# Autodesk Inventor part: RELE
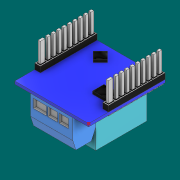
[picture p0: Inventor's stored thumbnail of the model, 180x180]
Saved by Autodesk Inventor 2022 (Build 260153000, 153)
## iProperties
Created: 2021-11
Part Number: RELE
Material: Generic
Document SubType Name: Modeling
Designer: santi
Density: 1 g/cm^3
Appearance: Default
Author: santi
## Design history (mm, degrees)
sketch "Sketch1"
  geometry: L1 (0, 0)-(0, -31); L2 (0, -31)-(26, -31); L3 (26, -31)-(26, 0); L4 (26, 0)-(0, 0)
  constraints: 8 end point, 3 perpendicular, 1 vertical
  dimensions: "d0" = 31 distance of L1.start L1.end; "d1" = 26 distance of L1.end L2.end
extrude "Extrusion1" new body sketch "Sketch1" distance "d2" = 1; taper "d3" = 0 deg
fillet "Fillet1" dims "d4" = 2
sketch "Sketch3"
  geometry: L1 (-26, 0)-(0, 0) reference; L2 (0, 0)-(0, 7); L3 (0, 0)-(0, 29) reference; L4 (0, 7)-(-2, 7); L5 (-2, 7)-(-2, 27); L6 (-2, 27)-(0, 27); L7 (0, 7)-(0, 27); L8 (-13, 0)-(-13, 9.207); L9 (-26, 0)-(-26, 7); L10 (-26, 0)-(-26, 29); L11 (-26, 7)-(-24, 7); L12 (-24, 7)-(-24, 27); L13 (-24, 27)-(-26, 27); L14 (-26, 7)-(-26, 27)
  constraints: 24 end point, 5 symmetric about line, 4 point on line, 3 perpendicular, 2 vertical, 1 midpoint
  dimensions: "d12" = 7 distance of L1.end L2.end; "d13" = 2 distance of L2.end L4.end; "d14" = 20 distance of L4.end L5.end
extrude "Extrusion3" join sketch "Sketch3" distance "d15" = 9; taper "d16" = 0 deg
sketch "Sketch5"
  geometry: L1 (9, 1)-(17, 1) reference; L2 (17, 1)-(9, 1); L3 (9, 1)-(11, 1); L4 (9, 1)-(10, 1); L5 (9, 1)-(9, 3) reference; L6 (13, 1)-(13, 2.179); L7 (17, 1)-(16, 1); L8 (17, 1)-(17, 3); A1 r 1 centre (10, 2) between (9, 2) and (10, 1); A2 r 1 centre (16, 2) between (16, 1) and (17, 2); 3 further points
  constraints: 12 end point, 4 point on circle, 4 symmetric about line, 3 midpoint, 2 centre point, 1 collinear, 1 point on line, 1 tangent, 1 vertical, 1 other
  dimensions: "d23" = 1 distance of L1.start L4.end
extrude "Extrusion5" cut sketch "Sketch5" distance "d24" = 5; taper "d25" = 0 deg
sketch "Sketch9"
  geometry: L1 (-24, 27)-(-26, 27) reference; L2 (-26, 27)-(-26, 7) reference; L3 (-26, 7)-(-24, 7) reference; L4 (-24, 7)-(-24, 27) reference; L5 (-25.7, 26.7)-(-24.3, 26.7); L6 (-24.3, 25.1)-(-24.3, 7.3); L7 (-24.3, 7.3)-(-25.7, 7.3); L8 (-25.7, 7.3)-(-25.7, 26.7); L9 (-24.3, 26.7)-(-24.3, 25.1); L10 (-24.3, 25.1)-(-25.7, 25.1); L11 (-25.7, 24.8)-(-24.3, 24.8); L12 (-24, 24.9)-(-24, 26.7); L13 (-25.7, 23.2)-(-24.3, 23.2); L14 (-25.7, 22.9)-(-24.3, 22.9); L15 (-25.7, 21.3)-(-24.3, 21.3); L16 (-25.7, 21)-(-24.3, 21); L17 (-25.7, 19.4)-(-24.3, 19.4); L18 (-25.7, 19.1)-(-24.3, 19.1); L19 (-25.7, 17.5)-(-24.3, 17.5); L20 (-25.7, 17.2)-(-24.3, 17.2); L21 (-25.7, 15.6)-(-24.3, 15.6); L22 (-25.7, 15.3)-(-24.3, 15.3); L23 (-25.7, 13.7)-(-24.3, 13.7); L24 (-25.7, 13.4)-(-24.3, 13.4); L25 (-25.7, 11.8)-(-24.3, 11.8); L26 (-25.7, 11.5)-(-24.3, 11.5); L27 (-25.7, 9.9)-(-24.3, 9.9); L28 (-25.7, 9.5)-(-24.3, 9.5); 34 further points
  constraints: 48 end point, 16 parallel, 2 point on line, 1 perpendicular, 1 other
  dimensions: "d38" = 0.3 distance between parallel lines of L1 L5; "d39" = 1.6 distance of L6.start L5.end; "d40" = 0.3 distance between parallel lines of L10 L11; "d41" = 1.6 distance between parallel lines of L11 L13; "d42" = 0.3 distance between parallel lines of L13 L14; "d43" = 1.6 distance between parallel lines of L14 L15; "d44" = 0.3 distance between parallel lines of L15 L16; "d45" = 1.6 distance between parallel lines of L16 L17; "d46" = 0.3 distance between parallel lines of L17 L18; "d47" = 1.6 distance between parallel lines of L18 L19; "d48" = 0.3 distance between parallel lines of L19 L20; "d49" = 1.6 distance between parallel lines of L20 L21; "d50" = 0.3 distance between parallel lines of L21 L22; "d51" = 1.6 distance between parallel lines of L22 L23; "d52" = 0.3 distance between parallel lines of L23 L24; "d53" = 1.6 distance between parallel lines of L24 L25; "d54" = 0.3 distance between parallel lines of L25 L26; "d55" = 1.6 distance between parallel lines of L26 L27; "d56" = 0.4 distance between parallel lines of L27 L28
extrude "Extrusion9" cut sketch "Sketch9" distance "d57" = 9; taper "d58" = 0 deg
sketch "Sketch10"
  geometry: L1 (-25.7, 13.4)-(-24.3, 13.4) reference; L2 (-24.3, 13.4)-(-24.3, 11.8) reference; L3 (-24.3, 11.8)-(-25.7, 11.8) reference; L4 (-25.7, 11.8)-(-25.7, 13.4) reference; L5 (-25.7, 21)-(-24.3, 21) reference; L6 (-24.3, 21)-(-24.3, 19.4) reference; L7 (-24.3, 19.4)-(-25.7, 19.4) reference; L8 (-25.7, 19.4)-(-25.7, 21) reference; L9 (-25.7, 25.1)-(-25.7, 26.7) reference; L10 (-25.7, 26.7)-(-24.3, 26.7) reference; L11 (-24.3, 26.7)-(-24.3, 25.1) reference; L12 (-24.3, 25.1)-(-25.7, 25.1) reference; L13 (-25.7, 19.1)-(-24.3, 19.1) reference; L14 (-24.3, 19.1)-(-24.3, 17.5) reference; L15 (-24.3, 17.5)-(-25.7, 17.5) reference; L16 (-25.7, 17.5)-(-25.7, 19.1) reference; L17 (-25.7, 11.5)-(-24.3, 11.5) reference; L18 (-24.3, 11.5)-(-24.3, 9.9) reference; L19 (-24.3, 9.9)-(-25.7, 9.9) reference; L20 (-25.7, 9.9)-(-25.7, 11.5) reference; L21 (-25.7, 15.3)-(-24.3, 15.3) reference; L22 (-24.3, 15.3)-(-24.3, 13.7) reference; L23 (-24.3, 13.7)-(-25.7, 13.7) reference; L24 (-25.7, 13.7)-(-25.7, 15.3) reference; L25 (-25.7, 22.9)-(-24.3, 22.9) reference; L26 (-24.3, 22.9)-(-24.3, 21.3) reference; L27 (-24.3, 21.3)-(-25.7, 21.3) reference; L28 (-25.7, 21.3)-(-25.7, 22.9) reference; L29 (-25.7, 24.8)-(-24.3, 24.8) reference; L30 (-24.3, 24.8)-(-24.3, 23.2) reference; L31 (-24.3, 23.2)-(-25.7, 23.2) reference; L32 (-25.7, 23.2)-(-25.7, 24.8) reference; L33 (-25.7, 17.2)-(-24.3, 17.2) reference; L34 (-24.3, 17.2)-(-24.3, 15.6) reference; L35 (-24.3, 15.6)-(-25.7, 15.6) reference; L36 (-25.7, 15.6)-(-25.7, 17.2) reference; L37 (-25.7, 9.5)-(-24.3, 9.5) reference; L38 (-24.3, 9.5)-(-24.3, 7.3) reference; L39 (-24.3, 7.3)-(-25.7, 7.3) reference; L40 (-25.7, 7.3)-(-25.7, 9.5) reference; L41 (-24, 27)-(-26, 27) reference; L42 (-26, 27)-(-26, 7) reference; L43 (-26, 7)-(-24, 7) reference; L44 (-24, 7)-(-24, 27) reference; L45 (-2, 31)-(-24, 31) reference; L46 (-13, 31)-(-13, 22.1); L47 (-1.7, 24.8)-(-1.7, 23.2); L48 (-2, 7)-(-2, 27); L49 (0, 27)-(0, 7); L50 (-1.7, 21)-(-1.7, 19.4); L51 (-0.3, 19.4)-(-0.3, 21); L52 (-0.3, 21)-(-1.7, 21); L53 (-1.7, 21.3)-(-0.3, 21.3); L54 (-1.7, 22.9)-(-1.7, 21.3); L55 (-0.3, 22.9)-(-1.7, 22.9); L56 (-0.3, 21.3)-(-0.3, 22.9); L57 (-1.7, 23.2)-(-0.3, 23.2); L58 (-0.3, 23.2)-(-0.3, 24.8); L59 (-1.7, 25.1)-(-0.3, 25.1); L60 (-2, 27)-(0, 27); L61 (-1.7, 13.4)-(-1.7, 11.8); L62 (-0.3, 11.8)-(-0.3, 13.4); L63 (-1.7, 11.8)-(-0.3, 11.8); L64 (-0.3, 13.4)-(-1.7, 13.4)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; 1 further point
  constraints: 90 end point, 44 symmetric about line, 1 midpoint, 1 vertical
extrude "Extrusion10" cut sketch "Sketch10" distance "d59" = 9; taper "d60" = 0 deg
sketch "Sketch12"
  geometry: 1 further point
sketch "Sketch13"
  geometry: L1 (-1.7, -22.9)-(-0.3, -22.9) reference; L2 (-0.3, -22.9)-(-0.3, -21.3) reference; L3 (-0.3, -21.3)-(-1.7, -21.3) reference; L4 (-1.7, -21.3)-(-1.7, -22.9) reference; L5 (-0.3, -13.7)-(-1.7, -13.7) reference; L6 (-1.7, -13.7)-(-1.7, -15.3) reference; L7 (-1.7, -15.3)-(-0.3, -15.3) reference; L8 (-0.3, -15.3)-(-0.3, -13.7) reference; L9 (-0.3, -7.3)-(-1.7, -7.3) reference; L10 (-1.7, -7.3)-(-1.7, -9.5) reference; L11 (-1.7, -9.5)-(-0.3, -9.5) reference; L12 (-0.3, -9.5)-(-0.3, -7.3) reference; L13 (-0.3, -15.6)-(-1.7, -15.6) reference; L14 (-1.7, -15.6)-(-1.7, -17.2) reference; L15 (-1.7, -17.2)-(-0.3, -17.2) reference; L16 (-0.3, -17.2)-(-0.3, -15.6) reference; L17 (-0.3, -24.8)-(-0.3, -23.2) reference; L18 (-0.3, -23.2)-(-1.7, -23.2) reference; L19 (-1.7, -23.2)-(-1.7, -24.8) reference; L20 (-1.7, -24.8)-(-0.3, -24.8) reference; L21 (-0.3, -21)-(-0.3, -19.4) reference; L22 (-0.3, -19.4)-(-1.7, -19.4) reference; L23 (-1.7, -19.4)-(-1.7, -21) reference; L24 (-1.7, -21)-(-0.3, -21) reference; L25 (-0.3, -13.4)-(-0.3, -11.8) reference; L26 (-0.3, -11.8)-(-1.7, -11.8) reference; L27 (-1.7, -11.8)-(-1.7, -13.4) reference; L28 (-1.7, -13.4)-(-0.3, -13.4) reference; L29 (-0.3, -9.9)-(-1.7, -9.9) reference; L30 (-1.7, -9.9)-(-1.7, -11.5) reference; L31 (-1.7, -11.5)-(-0.3, -11.5) reference; L32 (-0.3, -11.5)-(-0.3, -9.9) reference; L33 (-0.3, -17.5)-(-1.7, -17.5) reference; L34 (-1.7, -17.5)-(-1.7, -19.1) reference; L35 (-1.7, -19.1)-(-0.3, -19.1) reference; L36 (-0.3, -19.1)-(-0.3, -17.5) reference; L37 (-1.7, -26.7)-(-0.3, -26.7) reference; L38 (-0.3, -26.7)-(-0.3, -25.1) reference; L39 (-0.3, -25.1)-(-1.7, -25.1) reference; L40 (-1.7, -25.1)-(-1.7, -26.7) reference; L41 (-2, -7)-(0, -7) reference; L42 (0, -7)-(0, -27) reference; L43 (0, -27)-(-2, -27) reference; L44 (-2, -27)-(-2, -7) reference; L45 (-25.7, -13.4)-(-24.3, -13.4) reference; L46 (-24.3, -13.4)-(-24.3, -11.8) reference; L47 (-24.3, -11.8)-(-25.7, -11.8) reference; L48 (-25.7, -11.8)-(-25.7, -13.4) reference; L49 (-25.7, -21)-(-24.3, -21) reference; L50 (-24.3, -21)-(-24.3, -19.4) reference; L51 (-24.3, -19.4)-(-25.7, -19.4) reference; L52 (-25.7, -19.4)-(-25.7, -21) reference; L53 (-25.7, -25.1)-(-25.7, -26.7) reference; L54 (-25.7, -26.7)-(-24.3, -26.7) reference; L55 (-24.3, -26.7)-(-24.3, -25.1) reference; L56 (-24.3, -25.1)-(-25.7, -25.1) reference; L57 (-25.7, -19.1)-(-24.3, -19.1) reference; L58 (-24.3, -19.1)-(-24.3, -17.5) reference; L59 (-24.3, -17.5)-(-25.7, -17.5) reference; L60 (-25.7, -17.5)-(-25.7, -19.1) reference; L61 (-25.7, -11.5)-(-24.3, -11.5) reference; L62 (-24.3, -11.5)-(-24.3, -9.9) reference; L63 (-24.3, -9.9)-(-25.7, -9.9) reference; L64 (-25.7, -9.9)-(-25.7, -11.5) reference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; 1 further point
extrude "Extrusion12" join sketch "Sketch13" distance "d65" = 1; taper "d66" = 0 deg
chamfer "Chamfer1" distance "d67" = 0.5; stored, may be unused: second distance "d68" = 2, angle "d69" = 45 deg
chamfer "Chamfer2" distance "d70" = 0.5; stored, may be unused: second distance "d71" = 2, angle "d72" = 45 deg
sketch "Sketch16"
  geometry: L1 (29, 1)-(29, 0) reference; L2 (27, 1)-(29, 1) reference; L3 (27, 1)-(27, 10) reference; L4 (7, 10)-(27, 10) reference; L5 (7, 1)-(7, 10) reference; L6 (0, 1)-(7, 1) reference; L7 (0, 0)-(0, 1) reference; L8 (0, 0)-(29, 0) reference; L9 (7, 1)-(27, 1) reference; L10 (27, 1)-(7, 1); 1 further point
  constraints: 2 end point, 1 collinear
extrude "Extrusion15" join sketch "Sketch16" distance "d81" = 0.01; taper "d82" = 0 deg
sketch "Sketch17"
  geometry: L1 (3.9, 10)-(3.9, 1) reference; L2 (22, 1)-(22, 10) reference; L3 (2, 10)-(22, 10) reference; L4 (2, 1)-(2, 10) reference; L5 (0, 1)-(2, 1) reference; L6 (0, 0)-(0, 1) reference; L7 (0, 0)-(29, 0) reference; L8 (22, 1)-(2, 1) reference; L9 (2, 1)-(22, 1); L10 (29, 0)-(29, 1) reference; L11 (22, 1)-(29, 1) reference; 2 further points
  constraints: 2 end point, 1 perpendicular
extrude "Extrusion16" join sketch "Sketch17" distance "d83" = 0.01; taper "d84" = 0 deg
sketch "Sketch20"
  geometry: L1 (-3.262, 9.702)-(-3.262, 13.702); L2 (-3.262, 13.702)-(-8.262, 13.702); L3 (-8.262, 13.702)-(-8.262, 9.702); L4 (-8.262, 9.702)-(-3.262, 9.702); L5 (-17.843, 24.471)-(-17.843, 19.471); L6 (-17.843, 21.971)-(-15.343, 21.971); L7 (-15.343, 21.971)-(-20.343, 21.971); L8 (-20.343, 21.971)-(-17.843, 24.471); L9 (-15.343, 21.971)-(-17.843, 19.471); L10 (-17.843, 24.471)-(-15.343, 21.971); L11 (-17.843, 19.471)-(-20.343, 21.971); 1 further point
  constraints: 22 end point, 3 perpendicular, 2 vertical, 1 horizontal, 1 midpoint, 1 point on line
  dimensions: "d92" = 4 distance of L1.start L1.end; "d93" = 5 distance of L1.end L2.end; "d94" = 5 distance of L5.start L5.end; "d95" = 2.5 distance of L6.start L6.end; "d96" = 5 distance of L6.end L7.end
extrude "Extrusion19" join sketch "Sketch20" distance "d97" = 1; taper "d98" = 0 deg
sketch "Sketch24"
  geometry: L1 (-24, 27)-(-26.01, 27) reference; L2 (0, 27)-(-26, 27); L3 (-30.405, 27.517)-(-28.202, 31.661); L4 (-28.202, 31.661)-(2.882, 32.204); L5 (2.882, 32.204)-(1.816, 27); L6 (1.816, 27)-(0, 27); L7 (-26, 27)-(-26, 7) reference; L8 (-26, 27)-(-29.304, 27); L9 (-29.304, 27)-(-30.405, 27.517); L10 (-26, 27.01)-(0, 27.01); L11 (0, 27.01)-(1.808, 27.01); L12 (1.808, 27.01)-(2.87, 32.194); L13 (2.87, 32.194)-(-28.196, 31.651); L14 (-28.196, 31.651)-(-30.391, 27.522); L15 (-30.391, 27.522)-(-29.301, 27.01); L16 (-29.301, 27.01)-(-26, 27.01); 1 further point
  constraints: 28 end point, 3 collinear, 1 horizontal, 1 point on line, 6 other
  dimensions: "d105" = 0.01 distance between parallel lines of L2 L10
extrude "Extrusion23" cut sketch "Sketch24" stored distance "d106" = 3; taper "d107" = 0 deg
sketch "Sketch25"
  geometry: L1 (0.01, -27.01)-(-26.01, -27.01) reference; L2 (-13, -27.01)-(-13, -26.01); L3 (-13, -26.01)-(-20.5, -26.01); L4 (-20.5, -26.01)-(-5.5, -26.01); L5 (-5.5, -26.01)-(-5.5, -8.01); L6 (-5.5, -8.01)-(-20.5, -8.01); L7 (-20.5, -8.01)-(-20.5, -26.01); 2 further points
  constraints: 12 end point, 3 perpendicular, 1 midpoint, 1 point on line, 1 vertical
  dimensions: "d108" = 1 distance of L2.start L2.end; "d109" = 7.5 distance of L2.end L3.end; "d110" = 15 distance of L3.end L4.end; "d111" = 18 distance of L4.end L5.end; "d112" = 15 distance of L5.end L6.end
extrude "Extrusion24" join sketch "Sketch25" distance "d113" = 14; taper "d114" = 0 deg
sketch "Sketch26"
  geometry: L1 (-25.7, 13.4)-(-24.3, 13.4) reference; L2 (-24.3, 13.4)-(-24.3, 11.8) reference; L3 (-24.3, 11.8)-(-25.7, 11.8) reference; L4 (-25.7, 11.8)-(-25.7, 13.4) reference; L5 (-25.7, 21)-(-24.3, 21) reference; L6 (-24.3, 21)-(-24.3, 19.4) reference; L7 (-24.3, 19.4)-(-25.7, 19.4) reference; L8 (-25.7, 19.4)-(-25.7, 21) reference; L9 (-25.7, 25.1)-(-25.7, 26.7) reference; L10 (-25.7, 26.7)-(-24.3, 26.7) reference; L11 (-24.3, 26.7)-(-24.3, 25.1) reference; L12 (-24.3, 25.1)-(-25.7, 25.1) reference; L13 (-25.7, 19.1)-(-24.3, 19.1) reference; L14 (-24.3, 19.1)-(-24.3, 17.5) reference; L15 (-24.3, 17.5)-(-25.7, 17.5) reference; L16 (-25.7, 17.5)-(-25.7, 19.1) reference; L17 (-25.7, 11.5)-(-24.3, 11.5) reference; L18 (-24.3, 11.5)-(-24.3, 9.9) reference; L19 (-24.3, 9.9)-(-25.7, 9.9) reference; L20 (-25.7, 9.9)-(-25.7, 11.5) reference; L21 (-25.7, 15.3)-(-24.3, 15.3) reference; L22 (-24.3, 15.3)-(-24.3, 13.7) reference; L23 (-24.3, 13.7)-(-25.7, 13.7) reference; L24 (-25.7, 13.7)-(-25.7, 15.3) reference; L25 (-25.7, 22.9)-(-24.3, 22.9) reference; L26 (-24.3, 22.9)-(-24.3, 21.3) reference; L27 (-24.3, 21.3)-(-25.7, 21.3) reference; L28 (-25.7, 21.3)-(-25.7, 22.9) reference; L29 (-25.7, 24.8)-(-24.3, 24.8) reference; L30 (-24.3, 24.8)-(-24.3, 23.2) reference; L31 (-24.3, 23.2)-(-25.7, 23.2) reference; L32 (-25.7, 23.2)-(-25.7, 24.8) reference; L33 (-25.7, 17.2)-(-24.3, 17.2) reference; L34 (-24.3, 17.2)-(-24.3, 15.6) reference; L35 (-24.3, 15.6)-(-25.7, 15.6) reference; L36 (-25.7, 15.6)-(-25.7, 17.2) reference; L37 (-25.7, 9.5)-(-24.3, 9.5) reference; L38 (-24.3, 9.5)-(-24.3, 7.3) reference; L39 (-24.3, 7.3)-(-25.7, 7.3) reference; L40 (-25.7, 7.3)-(-25.7, 9.5) reference; L41 (-24, 27)-(-26.01, 27) reference; L42 (-24, 7)-(-24, 27) reference; L43 (-1.7, 22.9)-(-0.3, 22.9) reference; L44 (-0.3, 22.9)-(-0.3, 21.3) reference; L45 (-0.3, 21.3)-(-1.7, 21.3) reference; L46 (-1.7, 21.3)-(-1.7, 22.9) reference; L47 (-0.3, 13.7)-(-1.7, 13.7) reference; L48 (-1.7, 13.7)-(-1.7, 15.3) reference; L49 (-1.7, 15.3)-(-0.3, 15.3) reference; L50 (-0.3, 15.3)-(-0.3, 13.7) reference; L51 (-0.3, 7.3)-(-1.7, 7.3) reference; L52 (-1.7, 7.3)-(-1.7, 9.5) reference; L53 (-1.7, 9.5)-(-0.3, 9.5) reference; L54 (-0.3, 9.5)-(-0.3, 7.3) reference; L55 (-0.3, 15.6)-(-1.7, 15.6) reference; L56 (-1.7, 15.6)-(-1.7, 17.2) reference; L57 (-1.7, 17.2)-(-0.3, 17.2) reference; L58 (-0.3, 17.2)-(-0.3, 15.6) reference; L59 (-0.3, 24.8)-(-0.3, 23.2) reference; L60 (-0.3, 23.2)-(-1.7, 23.2) reference; L61 (-1.7, 23.2)-(-1.7, 24.8) reference; L62 (-1.7, 24.8)-(-0.3, 24.8) reference; L63 (-0.3, 21)-(-0.3, 19.4) reference; L64 (-0.3, 19.4)-(-1.7, 19.4) reference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; 1 further point
extrude "Extrusion25" cut sketch "Sketch26" distance "d115" = 7; taper "d116" = 0 deg
sketch "Sketch27"
  geometry: L1 (-0.3, 26.7)-(-0.3, 25.1) reference; L2 (-1.7, 26.7)-(-0.3, 26.7) reference; L3 (-1.7, 25.1)-(-1.7, 26.7) reference; L4 (-0.3, 25.1)-(-1.7, 25.1) reference; L5 (-0.3, 23.2)-(-1.7, 23.2) reference; L6 (-0.3, 24.8)-(-0.3, 23.2) reference; L7 (-1.7, 24.8)-(-0.3, 24.8) reference; L8 (-1.7, 23.2)-(-1.7, 24.8) reference; L9 (-0.3, 22.9)-(-0.3, 21.3) reference; L10 (-1.7, 22.9)-(-0.3, 22.9) reference; L11 (-1.7, 21.3)-(-1.7, 22.9) reference; L12 (-0.3, 21.3)-(-1.7, 21.3) reference; L13 (-0.3, 19.4)-(-1.7, 19.4) reference; L14 (-0.3, 21)-(-0.3, 19.4) reference; L15 (-1.7, 21)-(-0.3, 21) reference; L16 (-1.7, 19.4)-(-1.7, 21) reference; L17 (-1.7, 17.5)-(-1.7, 19.1) reference; L18 (-0.3, 17.5)-(-1.7, 17.5) reference; L19 (-0.3, 19.1)-(-0.3, 17.5) reference; L20 (-1.7, 19.1)-(-0.3, 19.1) reference; L21 (-1.7, 15.6)-(-1.7, 17.2) reference; L22 (-0.3, 15.6)-(-1.7, 15.6) reference; L23 (-0.3, 17.2)-(-0.3, 15.6) reference; L24 (-1.7, 17.2)-(-0.3, 17.2) reference; L25 (-1.7, 13.7)-(-1.7, 15.3) reference; L26 (-0.3, 13.7)-(-1.7, 13.7) reference; L27 (-0.3, 15.3)-(-0.3, 13.7) reference; L28 (-1.7, 15.3)-(-0.3, 15.3) reference; L29 (-0.3, 11.8)-(-1.7, 11.8) reference; L30 (-0.3, 13.4)-(-0.3, 11.8) reference; L31 (-1.7, 13.4)-(-0.3, 13.4) reference; L32 (-1.7, 11.8)-(-1.7, 13.4) reference; L33 (-1.7, 9.9)-(-1.7, 11.5) reference; L34 (-0.3, 9.9)-(-1.7, 9.9) reference; L35 (-0.3, 11.5)-(-0.3, 9.9) reference; L36 (-1.7, 11.5)-(-0.3, 11.5) reference; L37 (-1.7, 7.3)-(-1.7, 9.5) reference; L38 (-0.3, 7.3)-(-1.7, 7.3) reference; L39 (-0.3, 9.5)-(-0.3, 7.3) reference; L40 (-1.7, 9.5)-(-0.3, 9.5) reference; L41 (-24.3, 9.5)-(-24.3, 7.3) reference; L42 (-25.7, 9.5)-(-24.3, 9.5) reference; L43 (-25.7, 7.3)-(-25.7, 9.5) reference; L44 (-24.3, 7.3)-(-25.7, 7.3) reference; L45 (-24.3, 11.5)-(-24.3, 9.9) reference; L46 (-25.7, 11.5)-(-24.3, 11.5) reference; L47 (-25.7, 9.9)-(-25.7, 11.5) reference; L48 (-24.3, 9.9)-(-25.7, 9.9) reference; L49 (-24.3, 13.4)-(-24.3, 11.8) reference; L50 (-25.7, 13.4)-(-24.3, 13.4) reference; L51 (-25.7, 11.8)-(-25.7, 13.4) reference; L52 (-24.3, 11.8)-(-25.7, 11.8) reference; L53 (-24.3, 15.3)-(-24.3, 13.7) reference; L54 (-25.7, 15.3)-(-24.3, 15.3) reference; L55 (-25.7, 13.7)-(-25.7, 15.3) reference; L56 (-24.3, 13.7)-(-25.7, 13.7) reference; L57 (-24.3, 17.2)-(-24.3, 15.6) reference; L58 (-25.7, 17.2)-(-24.3, 17.2) reference; L59 (-25.7, 15.6)-(-25.7, 17.2) reference; L60 (-24.3, 15.6)-(-25.7, 15.6) reference; L61 (-24.3, 19.1)-(-24.3, 17.5) reference; L62 (-25.7, 19.1)-(-24.3, 19.1) reference; L63 (-25.7, 17.5)-(-25.7, 19.1) reference; L64 (-24.3, 17.5)-(-25.7, 17.5) reference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; 1 further point
  constraints: 160 end point, 60 other
  dimensions: "d117" = 0.3 distance between parallel lines of L79 L85; "d118" = 0.3 distance between parallel lines of L75 L89; "d119" = 0.3 distance between parallel lines of L71 L93; "d120" = 0.3 distance between parallel lines of L67 L97; "d121" = 0.3 distance between parallel lines of L63 L101; "d122" = 0.3 distance between parallel lines of L59 L105; "d123" = 0.3 distance between parallel lines of L55 L109; "d124" = 0.3 distance between parallel lines of L51 L113; "d125" = 0.3 distance between parallel lines of L47 L117; "d126" = 0.3 distance between parallel lines of L43 L121; "d127" = 0.3 distance between parallel lines of L40 L125; "d128" = 0.3 distance between parallel lines of L33 L126; "d129" = 0.3 distance between parallel lines of L32 L133; "d130" = 0.3 distance between parallel lines of L25 L134; "d131" = 0.3 distance between parallel lines of L21 L138; "d132" = 0.3 distance between parallel lines of L17 L142; "d133" = 0.3 distance between parallel lines of L16 L149; "d134" = 0.3 distance between parallel lines of L11 L153; "d135" = 0.3 distance between parallel lines of L8 L157; "d136" = 0.3 distance between parallel lines of L3 L161
extrude "Extrusion26" join sketch "Sketch27" distance "d137" = 7; taper "d138" = 0 deg
sketch "Sketch28"
  geometry: L1 (-8.01, 0)-(19, 0) reference; L2 (0, 0)-(0, -14) reference; L3 (0, 0)-(-8, 0); L4 (-8.01, 0)-(-1.01, 0) reference; L5 (0, 0)-(-8, 0); L6 (-8.01, 1)-(-8.01, 0) reference; L7 (-8.01, -2.15)-(-8.01, 0); L8 (-8.01, 0)-(-8.01, -7); L9 (-8.01, -7)-(-6.982, -10.345); L10 (-6.982, -10.345)-(-1.536, -10.345); L11 (-1.536, -10.345)-(0, -7); L12 (0, -7)-(0, 0); L13 (-0.71, 0)-(1.49, 0) reference; 1 further point
  constraints: 16 end point, 2 perpendicular, 2 point on line, 1 collinear, 1 midpoint, 1 vertical
  dimensions: "d139" = 8 distance of L2.start L3.end; "d140" = 7 distance of L1.start L8.end; "d141" = 3.5 distance of L8.end L9.end
extrude "Extrusion27" join sketch "Sketch28" distance "d142" = 15; taper "d143" = 0 deg
workplane "Work Plane1"
sketch "Sketch29"
  geometry: L1 (3.5, -7)-(3.5, 0) reference; L2 (18.5, -7)-(3.5, -7) reference; L3 (18.5, 0)-(18.5, -7) reference; L4 (24.01, 1)-(24.01, 0) reference; L5 (3.5, -7)-(3.5, 0) reference; L6 (18.5, 0)-(3.5, 0); L7 (24.01, 0)-(18.5, 0) reference; L8 (24.01, 1)-(-2.01, 1) reference; L9 (-2.01, 0)-(-2.01, 1) reference; L10 (3.5, 0)-(-2.01, 0) reference; 1 further point
  constraints: 2 end point, 1 horizontal
extrude "Extrusion28" cut sketch "Sketch29" distance "d144" = 0.01; taper "d145" = 0 deg
sketch "Sketch30"
  geometry: L1 (0, 14)-(26, 14) reference; L2 (0, 14)-(0, 0) reference; L3 (18, 0)-(0, 0) reference; L4 (18, 7)-(18, 0) reference; L5 (18, 7)-(19.536, 3.655) reference; L6 (19.536, 3.655)-(24.982, 3.655) reference; L7 (24.982, 3.655)-(26.01, 7) reference; L8 (18, 7)-(18, 0) reference; L9 (18, 7)-(18, 14); L10 (18.71, 14)-(16.51, 14) reference; L11 (26, 7)-(26, 14) reference; L12 (26.01, 7)-(26, 7) reference; 2 further points
  constraints: 2 end point, 1 perpendicular, 1 point on line
extrude "Extrusion29" cut sketch "Sketch30" distance "d146" = 0.01; taper "d147" = 0 deg
sketch "Sketch31"
  geometry: L1 (-26.01, 7)-(-24.982, 3.655) reference; L2 (-24.982, 3.655)-(-19.536, 3.655) reference; L3 (-19.536, 3.655)-(-18, 7) reference; L4 (-18, 7)-(-18, 0) reference; L5 (0, 0)-(-18, 0) reference; L6 (0, 14)-(0, 0) reference; L7 (-26, 14)-(0, 14) reference; L8 (-18, 7)-(-18, 0) reference; L9 (-18, 7)-(-18, 14); L10 (-18.71, 14)-(-16.51, 14) reference; L11 (-26, 7)-(-26.01, 7) reference; L12 (-26, 14)-(-26, 7) reference; 2 further points
  constraints: 2 end point, 1 perpendicular, 1 point on line
extrude "Extrusion30" cut sketch "Sketch31" distance "d148" = 0.01; taper "d149" = 0 deg
sketch "Sketch32"
  geometry: L1 (22, 3)-(2, 3) reference; L2 (2, 3)-(2, 1) reference; L3 (2, 1)-(1.99, 1) reference; L4 (1.99, 1)-(1.99, 0) reference; L5 (1.99, 0)-(29, 0) reference; L6 (29, 0)-(29, 1) reference; L7 (29, 1)-(22, 1) reference; L8 (22, 1)-(22, 3) reference; L9 (2, 1)-(22, 1) reference; L10 (22, 1)-(2, 1); 1 further point
  constraints: 2 end point, 1 collinear
extrude "Extrusion31" join sketch "Sketch32" distance "d150" = 0.01; taper "d151" = 0 deg
sketch "Sketch33"
  geometry: L1 (24.982, 3.655)-(19.536, 3.655) reference; L2 (26.01, 7)-(24.982, 3.655) reference; L3 (26, 7)-(26.01, 7) reference; L4 (26, 14)-(26, 7) reference; L5 (0, 14)-(26, 14) reference; L6 (0, 0)-(0, 14) reference; L7 (18, 0)-(0, 0) reference; L8 (18, 7)-(18, 0) reference; L9 (19.536, 3.655)-(18, 7) reference; L10 (18, 14)-(18, 7) reference; 1 further point
extrude "Extrusion32" cut sketch "Sketch33" distance "d152" = 0.01; taper "d153" = 0 deg
sketch "Sketch34"
  geometry: C1 r 1.5 at (-7.485, 3.12); C2 r 1.5 at (-11.924, 3.12); C3 r 1.5 at (-2.895, 3.12); 1 further point
  constraints: 3 centre point
  dimensions: "d154" = 3 diameter of C1; "d155" = 3 diameter of C2; "d156" = 3 diameter of C3
extrude "Extrusion33" cut sketch "Sketch34" distance "d157" = 2; taper "d158" = 0 deg
sketch "Sketch35"
  geometry: L1 (3.52, 0)-(3.52, -7) reference; L2 (18.49, -7)-(3.52, -7) reference; L3 (18.49, -7)-(18.49, 0) reference; L4 (3.52, 0)-(18.49, 0) reference; L5 (4.52, -6)-(4.52, -1); L6 (4.52, -1)-(17.49, -1); L7 (17.49, -1)-(17.49, -6); L8 (17.49, -6)-(4.52, -6); L9 (17.49, -4.063)-(4.52, -4.063); L10 (11.005, -4.063)-(17.49, -4.063); L11 (14.247, -4.063)-(14.247, -1); L12 (11.005, -4.063)-(4.52, -4.063); L13 (7.763, -4.063)-(7.763, -1); L14 (16.948, -4.063)-(16.948, -1); L15 (13.574, -4.063)-(13.574, -1); L16 (9.601, -4.063)-(9.601, -1); L17 (9.163, -4.063)-(9.163, -1); L18 (13.055, -4.063)-(13.055, -1); 11 further points
  constraints: 28 end point, 5 parallel, 4 point on line, 3 midpoint, 3 perpendicular, 2 collinear, 3 other
  dimensions: "d159" = 1 distance between parallel lines of L2 L8
extrude "Extrusion34" cut sketch "Sketch35" distance "d160" = 1; taper "d161" = 0 deg
body "Solid1"
node "Projected Loop1"
node "Projected Loop2"
node "Projected Loop3"
node "Projected Loop4"
node "Projected Loop5"
node "Projected Loop6"
node "Projected Loop10"
node "Projected Loop11"
node "Projected Loop12"
node "Projected Loop13"
node "Projected Loop14"
node "Projected Loop15"
node "Projected Loop16"
node "Projected Loop17"
node "Projected Loop18"
node "Projected Loop19"
node "Projected Loop20"
node "Projected Loop21"
node "Projected Loop22"
node "Projected Loop23"
node "Projected Loop24"
node "Projected Loop25"
node "Projected Loop26"
node "Projected Loop27"
node "Projected Loop28"
node "Projected Loop29"
node "Projected Loop30"
node "Projected Loop31"
node "Projected Loop32"
node "Projected Loop33"
node "Projected Loop34"
node "Projected Loop35"
node "Projected Loop36"
node "Projected Loop37"
